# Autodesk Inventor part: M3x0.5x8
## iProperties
Created: 2009-02
Part Number: M3x0.5x8
Material: 강, 연강
Description: 깊은 그루브 볼 베어링
Document SubType Name: Modeling
Standard: KS B 2023
Designer: KYOUNG IL JANG
Standards Organization: KS
Language: ko-KR
Size Designation: 6202 - 15 x 35 x 11
Categories: <MemberInstance><Categories><Category DisplayName="샤프트 부품" InternalName="7f7aeb1f-a693-4053-b835-cee3144e0d98" Mnemonic="SHFT"><Category DisplayName="베어링" Inter
Density: 7.86 g/cm^3
Mass: 45.8725 g
Surface Area: 51.5584 cm^2
Volume: 5.83619 cm^3
Vendor: CBT Solutions
Company: 한국ATC센터
IsCustomPart: 1
Author: KYOUNG IL JANG
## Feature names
1. IDS_ARRAYBALL[SIMPL:T] [Circular Pattern]
